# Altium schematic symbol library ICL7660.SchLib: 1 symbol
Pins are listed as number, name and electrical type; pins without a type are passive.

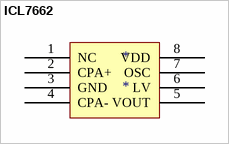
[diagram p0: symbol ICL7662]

## ICL7662
designator *
footprint DIP-8
footprint ILEAD8
pins: 1 NC, 2 CPA+, 3 GND, 4 CPA-, 5 VOUT, 6 LV, 7 OSC, 8 VDD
